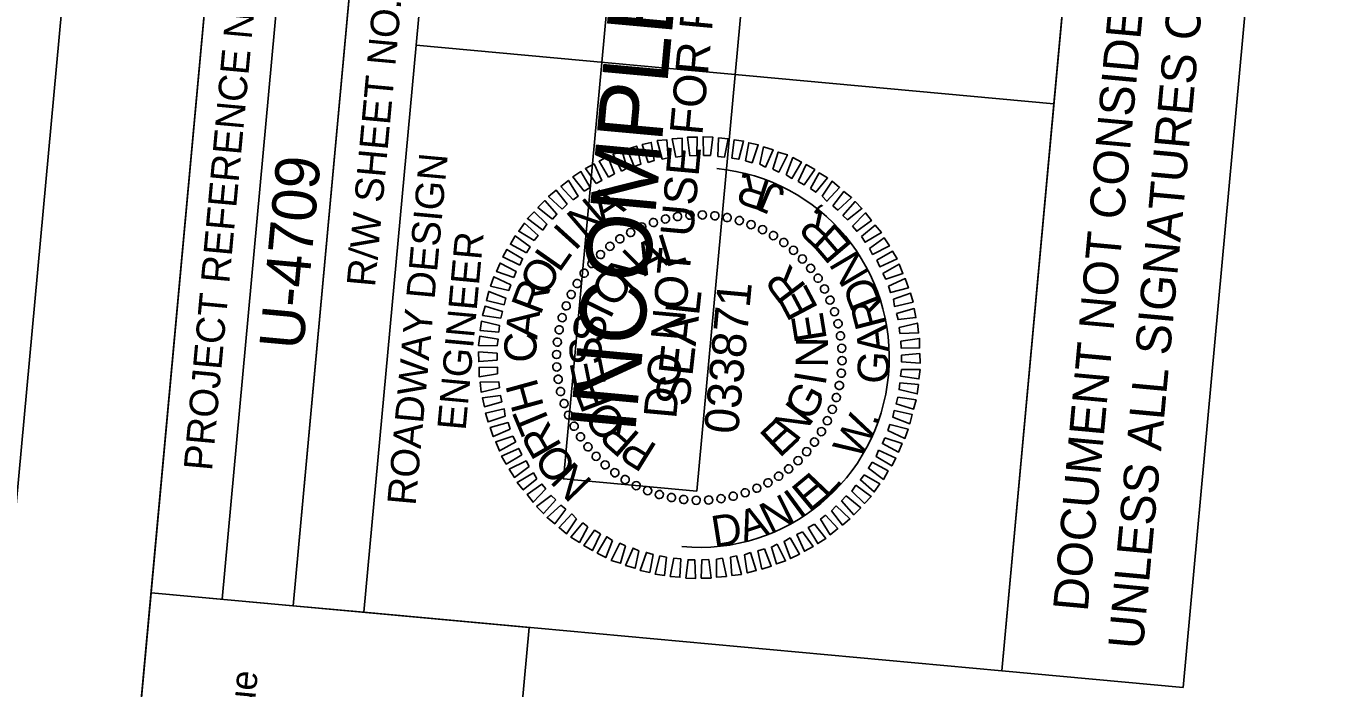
# Model space of a CAD drawing. Extents: x 2011671 to 2012922, y 444781 to 446720.
# Drawn here: x 2011808.5 to 2012036.3, y 446477.1 to 446593.4 of the extents above; entities that cross this region are included whole.
import ezdxf

# ---------------------------------------------------------------- set-up
doc = ezdxf.new("R2010")
doc.units = 0
for name, color, linetype in [('Old_Level_2', 7, 'Continuous'), ('Old_Level_58', 7, 'Continuous'), ('Scratch_Level_0', 7, 'Continuous'), ('Sheet Data Field CELL', 7, 'Continuous'), ('Sheet Plan And Profile CELL', 7, 'Continuous'), ('Sheet Plot Border Outside CELL', 7, 'Continuous'), ('Sheet Professional Seal CELL', 7, 'Continuous'), ('Sheet Profile Grid Minor CELL', 7, 'Continuous'), ('Sheet Sticker Exception Certification CELL', 7, 'Continuous'), ('Sheet Sticker Incomplete CELL', 7, 'Continuous')]:
    doc.layers.add(name, color=color, linetype=linetype)

msp = doc.modelspace()

# ---------------------------------------------------------------- linework, layer by layer
at = {"layer": 'Old_Level_58'}
msp.add_lwpolyline([(2011812.16, 446294.64), (2011830.48, 446493.85), (2011896.89, 446487.74), (2011878.57, 446288.53)], close=True, dxfattribs=at)
at = {"layer": 'Scratch_Level_0'}
msp.add_arc((2011926.77, 446535.16), 33.36, 264.7467, 84.7467, dxfattribs=at)
at = {"layer": 'Sheet Plan And Profile CELL'}
for p, q in [((2011842.98, 446492.7), (2011861.29, 446691.91)), ((2011855.42, 446491.55), (2011873.74, 446690.76)), ((2011877.03, 446590.04), (2011989.01, 446579.74)), ((2011855.42, 446491.55), (2011867.87, 446490.41))]:
    msp.add_line(p, q, dxfattribs=at)
for points in [[(2011848.79, 446693.05), (2011711.46, 445199.36), (2012757.04, 445103.22), (2012894.38, 446596.92)], [(2011830.48, 446493.85), (2011848.79, 446693.05), (2011873.74, 446690.76), (2011855.42, 446491.55)], [(2011877.03, 446590.04), (2011886.19, 446689.62), (2011998.21, 446679.32), (2011989.06, 446579.74)], [(2011867.87, 446490.41), (2011877.03, 446590.04), (2011989.06, 446579.74), (2011979.9, 446480.11)]]:
    msp.add_lwpolyline(points, close=True, dxfattribs=at)
at = {"layer": 'Sheet Plot Border Outside CELL'}
msp.add_lwpolyline([(2012765.92, 444926.66), (2012921.57, 446619.52), (2011826.19, 446720.24), (2011670.54, 445027.38)], close=True, dxfattribs=at)
at = {"layer": 'Sheet Professional Seal CELL'}
for p, q in [((2011922.92, 446559.97), (2011922.92, 446559.97)), ((2011925.15, 446560.17), (2011925.15, 446560.17)), ((2011927.32, 446560.27), (2011927.32, 446560.27)), ((2011929.51, 446560.12), (2011929.51, 446560.12)), ((2011931.69, 446559.77), (2011931.69, 446559.77)), ((2011916.68, 446558.13), (2011916.68, 446558.13)), ((2011918.71, 446558.95), (2011918.71, 446558.95)), ((2011920.78, 446559.56), (2011920.78, 446559.56)), ((2011933.8, 446559.22), (2011933.8, 446559.22)), ((2011935.85, 446558.58), (2011935.85, 446558.58)), ((2011937.88, 446557.69), (2011937.88, 446557.69)), ((2011912.82, 446556.08), (2011912.82, 446556.08)), ((2011914.68, 446557.16), (2011914.68, 446557.16)), ((2011939.78, 446556.61), (2011939.78, 446556.61)), ((2011941.64, 446555.44), (2011941.64, 446555.44)), ((2011909.41, 446553.33), (2011909.41, 446553.33)), ((2011911.04, 446554.73), (2011911.04, 446554.73)), ((2011943.31, 446554.03), (2011943.31, 446554.03)), ((2011907.9, 446551.71), (2011907.9, 446551.71)), ((2011944.93, 446552.52), (2011944.93, 446552.52)), ((2011946.34, 446550.89), (2011946.34, 446550.89)), ((2011906.49, 446550.03), (2011906.49, 446550.03)), ((2011947.68, 446549.11), (2011947.68, 446549.11)), ((2011904.24, 446546.27), (2011904.24, 446546.27)), ((2011905.32, 446548.18), (2011905.32, 446548.18)), ((2011948.77, 446547.25), (2011948.77, 446547.25)), ((2011903.35, 446544.24), (2011903.35, 446544.24)), ((2011949.74, 446545.25), (2011949.74, 446545.25)), ((2011902.71, 446542.19), (2011902.71, 446542.19)), ((2011950.55, 446543.22), (2011950.55, 446543.22)), ((2011902.16, 446540.09), (2011902.16, 446540.09)), ((2011951.17, 446541.15), (2011951.17, 446541.15)), ((2011901.81, 446537.91), (2011901.81, 446537.91)), ((2011951.57, 446539.01), (2011951.57, 446539.01)), ((2011901.66, 446535.71), (2011901.66, 446535.71)), ((2011926.77, 446535.16), (2011926.77, 446535.16)), ((2011951.77, 446536.78), (2011951.77, 446536.78)), ((2011901.76, 446533.55), (2011901.76, 446533.55)), ((2011951.72, 446532.42), (2011951.72, 446532.42)), ((2011951.87, 446534.61), (2011951.87, 446534.61)), ((2011901.96, 446531.32), (2011901.96, 446531.32)), ((2011951.37, 446530.24), (2011951.37, 446530.24)), ((2011902.37, 446529.17), (2011902.37, 446529.17)), ((2011950.82, 446528.13), (2011950.82, 446528.13)), ((2011902.98, 446527.11), (2011902.98, 446527.11)), ((2011950.18, 446526.08), (2011950.18, 446526.08)), ((2011903.8, 446525.07), (2011903.8, 446525.07)), ((2011949.29, 446524.05), (2011949.29, 446524.05)), ((2011904.77, 446523.08), (2011904.77, 446523.08)), ((2011905.85, 446521.22), (2011905.85, 446521.22)), ((2011948.21, 446522.14), (2011948.21, 446522.14)), ((2011907.19, 446519.44), (2011907.19, 446519.44)), ((2011947.04, 446520.29), (2011947.04, 446520.29)), ((2011908.6, 446517.8), (2011908.6, 446517.8)), ((2011944.13, 446517), (2011944.13, 446517)), ((2011945.63, 446518.62), (2011945.63, 446518.62)), ((2011910.22, 446516.3), (2011910.22, 446516.3)), ((2011911.9, 446514.89), (2011911.9, 446514.89)), ((2011940.71, 446514.25), (2011940.71, 446514.25)), ((2011942.49, 446515.59), (2011942.49, 446515.59)), ((2011913.75, 446513.71), (2011913.75, 446513.71)), ((2011915.66, 446512.64), (2011915.66, 446512.64)), ((2011936.86, 446512.19), (2011936.86, 446512.19)), ((2011938.85, 446513.16), (2011938.85, 446513.16)), ((2011917.68, 446511.75), (2011917.68, 446511.75)), ((2011919.73, 446511.11), (2011919.73, 446511.11)), ((2011921.84, 446510.56), (2011921.84, 446510.56)), ((2011924.02, 446510.21), (2011924.02, 446510.21)), ((2011926.22, 446510.06), (2011926.22, 446510.06)), ((2011928.38, 446510.16), (2011928.38, 446510.16)), ((2011930.61, 446510.36), (2011930.61, 446510.36)), ((2011932.76, 446510.76), (2011932.76, 446510.76)), ((2011934.82, 446511.38), (2011934.82, 446511.38))]:
    msp.add_line(p, q, dxfattribs=at)
for points in [[(2011920.23, 446570.01), (2011919.38, 446573.3), (2011921.05, 446573.45), (2011921.31, 446570.26)], [(2011922.67, 446570.39), (2011922.02, 446573.61), (2011923.74, 446573.75), (2011923.75, 446570.59)], [(2011925.11, 446570.61), (2011924.71, 446573.91), (2011926.41, 446573.91), (2011926.32, 446570.7)], [(2011927.52, 446570.69), (2011927.42, 446573.97), (2011929.12, 446573.91), (2011928.73, 446570.68)], [(2011930.02, 446570.51), (2011930.16, 446573.76), (2011931.86, 446573.61), (2011931.21, 446570.4)], [(2011932.5, 446570.23), (2011932.9, 446573.46), (2011934.53, 446573.21), (2011933.69, 446570.03)], [(2011913.11, 446567.95), (2011911.62, 446570.9), (2011913.23, 446571.4), (2011914.11, 446568.46)], [(2011915.34, 446568.75), (2011914.12, 446571.82), (2011915.77, 446572.33), (2011916.48, 446569.15)], [(2011917.77, 446569.43), (2011916.75, 446572.59), (2011918.34, 446572.99), (2011918.86, 446569.83)], [(2011934.87, 446569.77), (2011935.46, 446572.93), (2011937.13, 446572.57), (2011936.04, 446569.41)], [(2011937.37, 446569.13), (2011938.05, 446572.18), (2011939.71, 446571.68), (2011938.38, 446568.64)], [(2011939.7, 446568.27), (2011940.63, 446571.29), (2011942.24, 446570.8), (2011940.71, 446567.77)], [(2011908.64, 446565.75), (2011906.77, 446568.38), (2011908.3, 446569.2), (2011909.64, 446566.26)], [(2011910.8, 446566.86), (2011909.15, 446569.67), (2011910.73, 446570.48), (2011911.86, 446567.46)], [(2011942.02, 446567.3), (2011943.2, 446570.31), (2011944.69, 446569.52), (2011943.02, 446566.66)], [(2011944.12, 446566.1), (2011945.55, 446569.09), (2011947.03, 446568.2), (2011945.17, 446565.5)], [(2011906.56, 446564.44), (2011904.53, 446566.93), (2011905.97, 446567.85), (2011907.62, 446565.04)], [(2011946.32, 446564.9), (2011947.83, 446567.62), (2011949.3, 446566.73), (2011947.21, 446564.21)], [(2011902.7, 446561.23), (2011900.3, 446563.5), (2011901.61, 446564.59), (2011903.54, 446562.1)], [(2011904.61, 446562.86), (2011902.47, 446565.21), (2011903.77, 446566.3), (2011905.47, 446563.53)], [(2011948.35, 446563.51), (2011950.1, 446566.16), (2011951.4, 446565.03), (2011949.18, 446562.63)], [(2011950.21, 446561.83), (2011952.15, 446564.36), (2011953.5, 446563.28), (2011951.09, 446561.09)], [(2011900.98, 446559.48), (2011898.42, 446561.57), (2011899.63, 446562.76), (2011901.77, 446560.36)], [(2011951.96, 446560.16), (2011954.14, 446562.57), (2011955.33, 446561.36), (2011952.79, 446559.38)], [(2011899.3, 446557.57), (2011896.58, 446559.58), (2011897.74, 446560.78), (2011900, 446558.61)], [(2011953.69, 446558.24), (2011955.97, 446560.6), (2011957, 446559.25), (2011954.42, 446557.37)], [(2011897.78, 446555.75), (2011895.07, 446557.36), (2011896.05, 446558.77), (2011898.46, 446556.64)], [(2011955.28, 446556.44), (2011957.68, 446558.43), (2011958.76, 446557.13), (2011955.89, 446555.43)], [(2011896.42, 446553.57), (2011893.6, 446555.08), (2011894.44, 446556.56), (2011897.07, 446554.61)], [(2011956.64, 446554.31), (2011959.23, 446556.23), (2011960.15, 446554.79), (2011957.21, 446553.3)], [(2011895.27, 446551.41), (2011892.24, 446552.85), (2011892.97, 446554.19), (2011895.73, 446552.53)], [(2011957.96, 446552.28), (2011960.67, 446553.89), (2011961.5, 446552.51), (2011958.46, 446551.13)], [(2011894.17, 446549.26), (2011891.15, 446550.29), (2011891.79, 446551.78), (2011894.61, 446550.27)], [(2011959.01, 446549.97), (2011961.87, 446551.57), (2011962.52, 446549.95), (2011959.52, 446548.97)], [(2011893.3, 446546.93), (2011890.11, 446547.72), (2011890.67, 446549.38), (2011893.65, 446547.95)], [(2011960.01, 446547.72), (2011962.94, 446549.06), (2011963.5, 446547.45), (2011960.35, 446546.59)], [(2011892.52, 446544.44), (2011889.38, 446545.18), (2011889.78, 446546.8), (2011892.78, 446545.62)], [(2011960.85, 446545.44), (2011963.86, 446546.46), (2011964.32, 446544.92), (2011961.03, 446544.16)], [(2011891.9, 446542.08), (2011888.69, 446542.58), (2011889.14, 446544.2), (2011892.21, 446543.26)], [(2011961.42, 446542.92), (2011964.52, 446543.79), (2011964.82, 446542.21), (2011961.67, 446541.84)], [(2011891.53, 446539.61), (2011888.29, 446539.91), (2011888.49, 446541.54), (2011891.68, 446540.8)], [(2011961.85, 446540.47), (2011965.08, 446541.23), (2011965.28, 446539.51), (2011962, 446539.4)], [(2011891.26, 446537.22), (2011888, 446537.27), (2011888.2, 446538.91), (2011891.42, 446538.41)], [(2011962.18, 446538.03), (2011965.44, 446538.54), (2011965.44, 446536.88), (2011962.22, 446536.82)], [(2011891.28, 446534.71), (2011888.04, 446534.46), (2011888, 446536.17), (2011891.24, 446535.92)], [(2011962.26, 446535.62), (2011965.49, 446535.87), (2011965.54, 446534.16), (2011962.3, 446534.41)], [(2011891.35, 446532.29), (2011888.1, 446531.79), (2011888.1, 446533.45), (2011891.32, 446533.5)], [(2011962.28, 446533.1), (2011965.54, 446533.05), (2011965.34, 446531.42), (2011962.12, 446531.91)], [(2011891.68, 446529.85), (2011888.45, 446529.1), (2011888.26, 446530.82), (2011891.53, 446530.92)], [(2011962.01, 446530.72), (2011965.24, 446530.42), (2011965.04, 446528.78), (2011961.85, 446529.53)], [(2011892.11, 446527.4), (2011889.02, 446526.53), (2011888.71, 446528.12), (2011891.86, 446528.48)], [(2011961.63, 446528.24), (2011964.85, 446527.74), (2011964.4, 446526.13), (2011961.32, 446527.06)], [(2011892.68, 446524.89), (2011889.68, 446523.86), (2011889.22, 446525.41), (2011892.5, 446526.16)], [(2011961.01, 446525.89), (2011964.16, 446525.15), (2011963.76, 446523.53), (2011960.75, 446524.71)], [(2011893.53, 446522.6), (2011890.59, 446521.27), (2011890.04, 446522.87), (2011893.18, 446523.74)], [(2011960.23, 446523.4), (2011963.42, 446522.6), (2011962.87, 446520.95), (2011959.88, 446522.38)], [(2011894.52, 446520.35), (2011891.67, 446518.76), (2011891.01, 446520.37), (2011894.01, 446521.35)], [(2011959.36, 446521.07), (2011962.38, 446520.04), (2011961.74, 446518.54), (2011958.92, 446520.06)], [(2011895.57, 446518.05), (2011892.86, 446516.44), (2011892.03, 446517.82), (2011895.07, 446519.2)], [(2011958.26, 446518.91), (2011961.29, 446517.48), (2011960.57, 446516.14), (2011957.81, 446517.8)], [(2011896.89, 446516.02), (2011894.3, 446514.1), (2011893.38, 446515.54), (2011896.33, 446517.02)], [(2011957.11, 446516.76), (2011959.93, 446515.24), (2011959.09, 446513.76), (2011956.46, 446515.71)], [(2011898.25, 446513.88), (2011895.86, 446511.9), (2011894.77, 446513.2), (2011897.64, 446514.89)], [(2011955.75, 446514.57), (2011958.47, 446512.97), (2011957.48, 446511.55), (2011955.07, 446513.68)], [(2011899.84, 446512.08), (2011897.57, 446509.73), (2011896.53, 446511.08), (2011899.12, 446512.95)], [(2011954.23, 446512.75), (2011956.96, 446510.75), (2011955.79, 446509.55), (2011953.53, 446511.71)], [(2011901.57, 446510.16), (2011899.39, 446507.75), (2011898.2, 446508.97), (2011900.74, 446510.94)], [(2011952.55, 446510.85), (2011955.12, 446508.76), (2011953.9, 446507.56), (2011951.76, 446509.97)], [(2011903.33, 446508.5), (2011901.39, 446505.96), (2011900.03, 446507.04), (2011902.44, 446509.23)], [(2011905.18, 446506.82), (2011903.43, 446504.17), (2011902.13, 446505.29), (2011904.36, 446507.7)], [(2011948.92, 446507.47), (2011951.07, 446505.11), (2011949.76, 446504.03), (2011948.06, 446506.79)], [(2011950.83, 446509.1), (2011953.23, 446506.82), (2011951.93, 446505.74), (2011950, 446508.22)], [(2011907.21, 446505.43), (2011905.71, 446502.7), (2011904.23, 446503.59), (2011906.32, 446506.11)], [(2011946.97, 446505.89), (2011949, 446503.39), (2011947.56, 446502.47), (2011945.91, 446505.28)], [(2011909.41, 446504.22), (2011907.98, 446501.24), (2011906.51, 446502.13), (2011908.36, 446504.82)], [(2011911.51, 446503.02), (2011910.33, 446500.02), (2011908.85, 446500.81), (2011910.51, 446503.67)], [(2011942.73, 446503.47), (2011944.38, 446500.65), (2011942.8, 446499.85), (2011941.67, 446502.86)], [(2011944.89, 446504.57), (2011946.76, 446501.94), (2011945.23, 446501.13), (2011943.89, 446504.06)], [(2011913.83, 446502.06), (2011912.9, 446499.03), (2011911.29, 446499.53), (2011912.82, 446502.55)], [(2011916.16, 446501.19), (2011915.48, 446498.14), (2011913.82, 446498.64), (2011915.15, 446501.69)], [(2011918.66, 446500.56), (2011918.07, 446497.4), (2011916.4, 446497.75), (2011917.49, 446500.92)], [(2011935.77, 446500.89), (2011936.78, 446497.74), (2011935.19, 446497.33), (2011934.68, 446500.49)], [(2011938.19, 446501.58), (2011939.41, 446498.5), (2011937.76, 446498), (2011937.05, 446501.18)], [(2011940.42, 446502.37), (2011941.91, 446499.43), (2011940.3, 446498.92), (2011939.42, 446501.86)], [(2011921.03, 446500.09), (2011920.63, 446496.86), (2011919, 446497.11), (2011919.85, 446500.3)], [(2011923.52, 446499.81), (2011923.37, 446496.56), (2011921.67, 446496.72), (2011922.32, 446499.92)], [(2011926.01, 446499.63), (2011926.11, 446496.36), (2011924.41, 446496.42), (2011924.81, 446499.64)], [(2011928.43, 446499.71), (2011928.83, 446496.41), (2011927.12, 446496.42), (2011927.21, 446499.62)], [(2011930.86, 446499.94), (2011931.52, 446496.72), (2011929.8, 446496.57), (2011929.79, 446499.74)], [(2011933.3, 446500.32), (2011934.16, 446497.03), (2011932.49, 446496.88), (2011932.23, 446500.07)]]:
    msp.add_lwpolyline(points, close=True, dxfattribs=at)
for centre, major_axis in [((2011918.71, 446558.91), (-0.231, 0.682)), ((2011920.81, 446559.52), (-0.171, 0.699)), ((2011922.95, 446559.95), (-0.109, 0.712)), ((2011925.13, 446560.19), (-0.047, 0.718)), ((2011927.31, 446560.24), (0.016, 0.72)), ((2011929.5, 446560.09), (0.078, 0.716)), ((2011931.66, 446559.76), (0.141, 0.706)), ((2011933.79, 446559.24), (0.202, 0.691)), ((2011914.7, 446557.15), (-0.346, 0.631)), ((2011916.67, 446558.12), (-0.29, 0.659)), ((2011935.86, 446558.54), (0.261, 0.671)), ((2011937.86, 446557.66), (0.318, 0.646)), ((2011939.78, 446556.6), (0.374, 0.616)), ((2011911.07, 446554.72), (-0.451, 0.562)), ((2011912.83, 446556.02), (-0.4, 0.599)), ((2011941.6, 446555.39), (0.426, 0.581)), ((2011909.42, 446553.28), (-0.498, 0.52)), ((2011943.3, 446554.02), (0.475, 0.541)), ((2011944.88, 446552.5), (0.52, 0.498)), ((2011906.54, 446549.99), (-0.581, 0.426)), ((2011907.91, 446551.7), (-0.541, 0.475)), ((2011946.33, 446550.86), (0.562, 0.451)), ((2011905.33, 446548.17), (-0.616, 0.374)), ((2011947.62, 446549.1), (0.599, 0.4)), ((2011904.27, 446546.26), (-0.646, 0.318)), ((2011948.76, 446547.22), (0.631, 0.346)), ((2011949.72, 446545.26), (0.659, 0.29)), ((2011903.39, 446544.25), (-0.671, 0.261)), ((2011950.52, 446543.22), (0.682, 0.231)), ((2011902.69, 446542.18), (-0.691, 0.202)), ((2011951.13, 446541.12), (0.699, 0.171)), ((2011902.17, 446540.06), (-0.706, 0.141)), ((2011951.55, 446538.98), (0.712, 0.109)), ((2011901.84, 446537.89), (-0.716, 0.078)), ((2011951.79, 446536.8), (0.718, 0.047)), ((2011901.69, 446535.71), (-0.72, 0.016)), ((2011951.84, 446534.61), (0.72, -0.016)), ((2011901.74, 446533.52), (-0.718, -0.047)), ((2011951.7, 446532.43), (0.716, -0.078)), ((2011901.98, 446531.35), (-0.712, -0.109)), ((2011951.36, 446530.27), (0.706, -0.141)), ((2011902.4, 446529.2), (-0.699, -0.171)), ((2011903.02, 446527.1), (-0.682, -0.231)), ((2011950.84, 446528.14), (0.691, -0.202)), ((2011903.81, 446525.06), (-0.659, -0.29)), ((2011950.14, 446526.07), (0.671, -0.261)), ((2011904.78, 446523.1), (-0.631, -0.346)), ((2011949.26, 446524.07), (0.646, -0.318)), ((2011905.91, 446521.23), (-0.599, -0.4)), ((2011946.99, 446520.33), (0.581, -0.426)), ((2011948.21, 446522.15), (0.616, -0.374)), ((2011907.21, 446519.47), (-0.562, -0.451)), ((2011945.62, 446518.63), (0.541, -0.475)), ((2011908.65, 446517.82), (-0.52, -0.498)), ((2011910.23, 446516.31), (-0.475, -0.541)), ((2011944.11, 446517.04), (0.498, -0.52)), ((2011911.94, 446514.94), (-0.426, -0.581)), ((2011913.75, 446513.72), (-0.374, -0.616)), ((2011940.7, 446514.31), (0.4, -0.599)), ((2011942.46, 446515.6), (0.451, -0.562)), ((2011915.67, 446512.67), (-0.318, -0.646)), ((2011917.68, 446511.79), (-0.261, -0.671)), ((2011919.75, 446511.09), (-0.202, -0.691)), ((2011934.83, 446511.41), (0.231, -0.682)), ((2011936.87, 446512.21), (0.29, -0.659)), ((2011938.83, 446513.17), (0.346, -0.631)), ((2011921.87, 446510.56), (-0.141, -0.706)), ((2011924.03, 446510.23), (-0.078, -0.716)), ((2011926.22, 446510.09), (-0.016, -0.72)), ((2011928.41, 446510.14), (0.047, -0.718)), ((2011930.58, 446510.37), (0.109, -0.712)), ((2011932.73, 446510.8), (0.171, -0.699))]:
    msp.add_ellipse(centre, major_axis=major_axis, ratio=0.999708, dxfattribs=at)
at = {"layer": 'Sheet Sticker Exception Certification CELL'}
for p, q in [((2011979.88, 446480.11), (2011998.2, 446679.32)), ((2012030.04, 446676.39), (2012011.73, 446477.18)), ((2012011.73, 446477.18), (2011979.88, 446480.11))]:
    msp.add_line(p, q, dxfattribs=at)
at = {"layer": 'Sheet Sticker Incomplete CELL'}
msp.add_lwpolyline([(2011926.32, 446511.7), (2011902.91, 446513.85), (2011916.37, 446660.23), (2011939.77, 446658.08)], close=True, dxfattribs=at)

# ---------------------------------------------------------------- texts
at = {"layer": 'Old_Level_2'}
msp.add_text('1 Glenwood Avenue', height=4.6576, rotation=84.7467, dxfattribs=at).set_placement((2011844.11, 446424.1))
at = {"layer": 'Sheet Data Field CELL'}
msp.add_text('U-4709', height=7.75, rotation=84.7467, dxfattribs=at).set_placement((2011857.18, 446536.38))
at = {"layer": 'Sheet Plan And Profile CELL'}
for s, height, p in [('PROJECT REFERENCE NO.', 5.0001, (2011841.17, 446515.16)), ('R/W SHEET NO.', 5.0001, (2011869.8, 446547.47)), ('ROADWAY DESIGN', 5.0001, (2011876.92, 446509.06)), ('ENGINEER', 5, (2011885.71, 446522.26))]:
    msp.add_text(s, height=height, rotation=84.7467, dxfattribs=at).set_placement(p)
at = {"layer": 'Sheet Professional Seal CELL'}
for s, height, rotation, p in [('A', 5.64, 33.3638, (2011909.87, 446558.41)), ('N', 5.64, 40.5656, (2011906.67, 446555.74)), ('I', 5.64, 47.7668, (2011904.93, 446553.74)), ('A', 5.64, 26.5069, (2011917.13, 446549.4)), ('L', 5.64, 17.1475, (2011920.74, 446551.03)), ('L', 5.64, 54.9675, (2011902.16, 446549.93)), ('N', 5.64, 45.2233, (2011914.28, 446546.8)), ('O', 5.64, 62.1678, (2011899.92, 446545.72)), ('R', 5.64, 127.2281, (2011945.73, 446547.58)), ('R', 5.64, 69.3678, (2011898.87, 446542.45)), ('O', 5.64, 54.5801, (2011911.98, 446543.65)), ('SEAL', 5.998, 83.7467, (2011924.96, 446526.44)), ('E', 5.64, 117.8707, (2011947.75, 446543.83)), ('I', 5.64, 63.9363, (2011911.1, 446541.72)), ('A', 5.64, 83.767, (2011898.28, 446538.28)), ('S', 5.64, 82.6471, (2011910.01, 446537.51)), ('E', 5.64, 99.1584, (2011949.2, 446538.37)), ('C', 5.64, 90.9665, (2011898.22, 446534.32)), ('S', 5.64, 92.0023, (2011909.73, 446533.92)), ('N', 5.64, 89.803, (2011949.35, 446533.39)), ('E', 5.64, 101.3577, (2011910.46, 446530.39)), ('I', 5.64, 80.4479, (2011948.89, 446530.07)), ('H', 5.64, 105.3661, (2011899.52, 446526.57)), ('F', 5.64, 110.7137, (2011911.66, 446527.06)), ('G', 5.64, 61.7369, (2011946.4, 446523.72)), ('T', 5.64, 112.5664, (2011900.86, 446523.18)), ('O', 5.64, 129.4279, (2011914.3, 446523.51)), ('N', 5.64, 52.3806, (2011943.81, 446520.14)), ('R', 5.64, 119.7672, (2011902.74, 446519.6)), ('R', 5.64, 138.7863, (2011916.58, 446521.54)), ('E', 5.64, 43.0235, (2011940.85, 446517.4)), ('O', 5.64, 126.9684, (2011905.51, 446515.88)), ('P', 5.64, 148.1455, (2011919.62, 446519.65)), ('N', 5.64, 134.1702, (2011908.19, 446513.32))]:
    msp.add_text(s, height=height, rotation=rotation, dxfattribs=at).set_placement(p)
at = {"layer": 'Sheet Profile Grid Minor CELL'}
for s, height, rotation, p in [('R', 5.5, 162.1007, (2011939.55, 446566.09)), ('.', 5.5, 169.0272, (2011935.73, 446567.41)), ('J', 5.5, 157.2322, (2011942.13, 446564.9)), (',', 5.5, 144.0519, (2011948.51, 446560.61)), ('R', 5.5, 137.1254, (2011951.42, 446557.8)), ('E', 5.5, 130.5425, (2011953.85, 446554.83)), ('N', 5.5, 120.6107, (2011956.84, 446549.86)), ('D', 5.5, 111.4661, (2011958.79, 446544.89)), ('033871', 5.998, 84.7467, (2011933.56, 446521.59)), ('R', 5.5, 104.5397, (2011959.73, 446540.96)), ('A', 5.5, 96.3539, (2011960.22, 446536.21)), ('G', 5.5, 86.4222, (2011959.9, 446530.42)), ('W', 5.5, 61.6358, (2011954.86, 446516.97)), ('.', 5.5, 73.2419, (2011957.95, 446522.99)), ('E', 5.5, 39.7975, (2011946.08, 446507.82)), ('L', 5.5, 46.3805, (2011949.08, 446510.22)), ('I', 5.5, 36.277, (2011944.36, 446506.69)), ('N', 5.5, 26.3453, (2011939.19, 446504.08)), ('D', 5.5, 9.0149, (2011929.36, 446501.79)), ('A', 5.5, 18.1595, (2011934.63, 446502.63))]:
    msp.add_text(s, height=height, rotation=rotation, dxfattribs=at).set_placement(p)
at = {"layer": 'Sheet Sticker Exception Certification CELL'}
for s, p in [('UNLESS ALL SIGNATURES COMPLETED', (2012004.66, 446483.75)), ('DOCUMENT NOT CONSIDERED FINAL', (2011994.97, 446490.4))]:
    msp.add_text(s, height=6.124, rotation=84.7467, dxfattribs=at).set_placement(p)
at = {"layer": 'Sheet Sticker Incomplete CELL'}
for s, height, p in [('INCOMPLETE PLANS', 11.52, (2011915.48, 446521.68)), ('DO NOT USE FOR R/W ACQUISITION', 5.76, (2011922.7, 446524.28))]:
    msp.add_text(s, height=height, rotation=84.7467, dxfattribs=at).set_placement(p)

doc.saveas('drawing.dxf')
